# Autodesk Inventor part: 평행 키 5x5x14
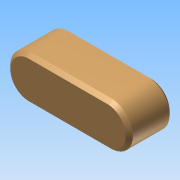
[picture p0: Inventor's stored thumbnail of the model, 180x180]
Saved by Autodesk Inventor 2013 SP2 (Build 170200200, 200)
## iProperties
Created: 2026-07
Part Number: 평행 키 5x5x14
Material: Generic
Document SubType Name: Modeling
Designer: 601
Density: 1 g/cm^3
Author: 601
변환 표준: STEP AP214IS
전처리기: Build: 200, Release: 2013 SP2 Update 6 - Date: Thu 07/17/2014
전송 단위: 밀리미터
불확실성: 0.01
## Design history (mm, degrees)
node "평행 키 5x5x141"
node "솔리드1"
node "기준1"
